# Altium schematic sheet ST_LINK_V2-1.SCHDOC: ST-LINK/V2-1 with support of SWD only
size A4; Date: 25-FEB-2015; Author: A.B; CompanyName: STMicroelectronics; Address1: 12, Rue Jules HOROWITZ; Address2: 38019 Grenoble; Address3: FRANCE; DocumentNumber: MB1191; Revision: B-02; SheetNumber: 2; SheetTotal: 13; Project: STM32F746G-DISCO
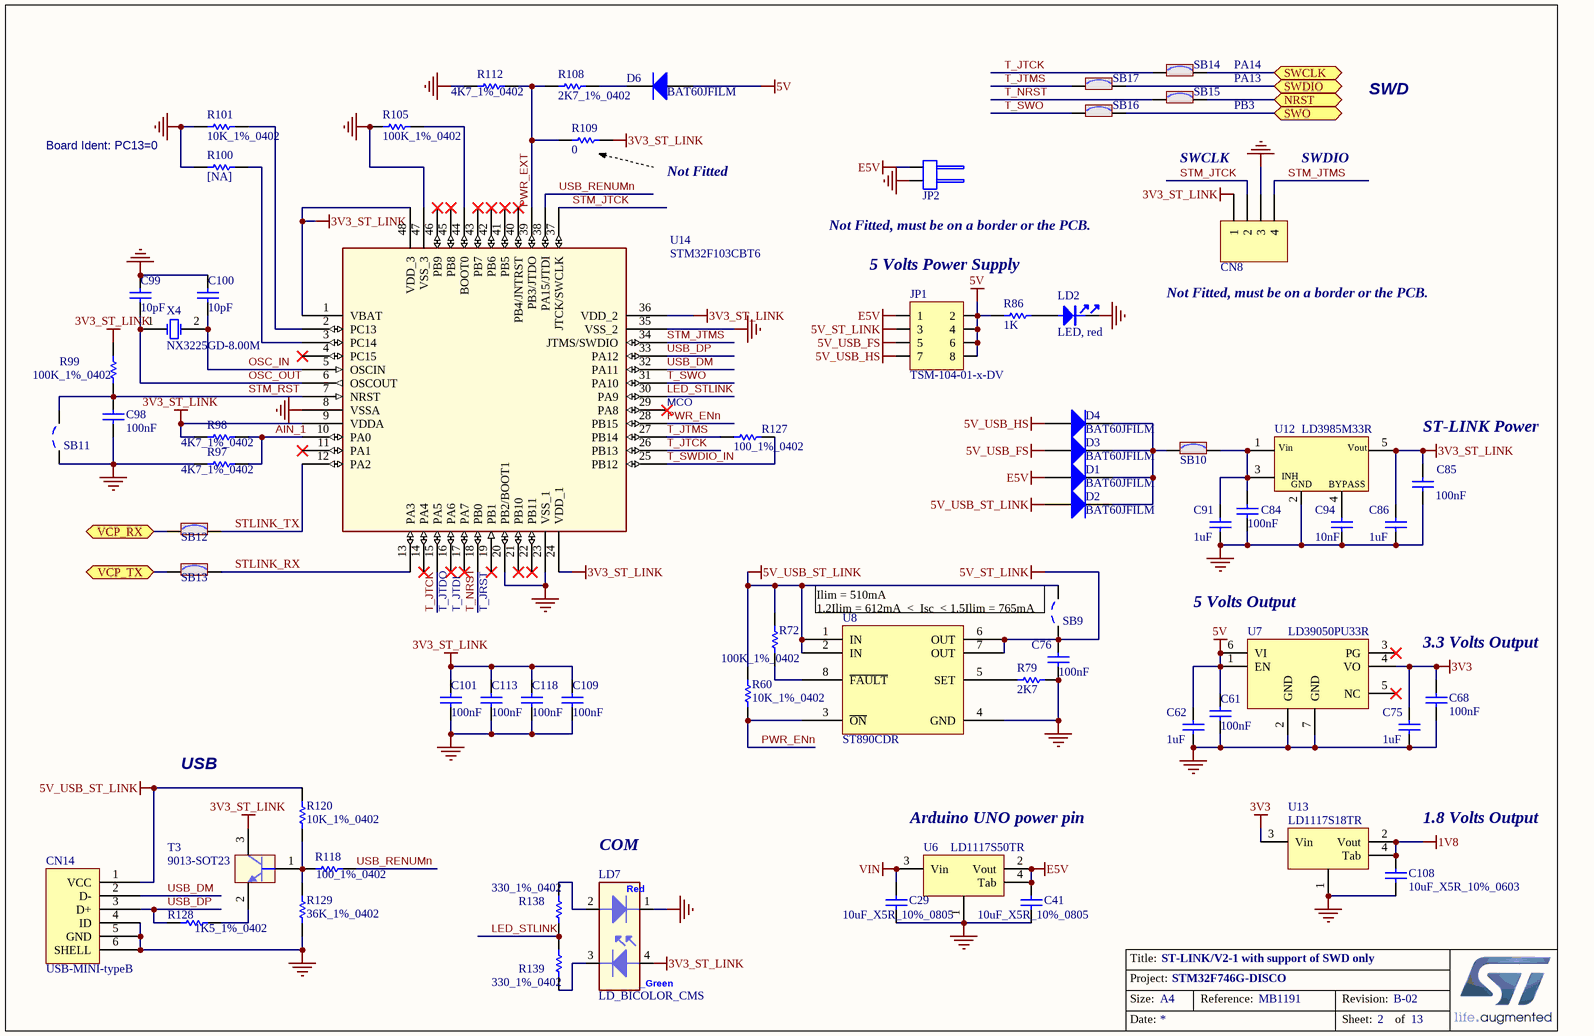
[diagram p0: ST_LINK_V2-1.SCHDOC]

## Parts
C29  10uF_X5R_10%_0805  [0805C]
C41  10uF_X5R_10%_0805  [0805C]
C61  100nF  [0402C]
C62  1uF  [0603C]
C68  100nF  [0402C]
C75  1uF  [0603C]
C76  100nF  [0402C]
C84  100nF  [0402C]
C85  100nF  [0402C]
C86  1uF  [0603C]
C91  1uF  [0603C]
C94  10nF  [0603C]
C98  100nF  [0402C]
C99  10pF  [0402C]
C100  10pF  [0402C]
C101  100nF  [0402C]
C108  10uF_X5R_10%_0603  [0603C]
C109  100nF  [0402C]
C113  100nF  [0402C]
C118  100nF  [0402C]
CN8  Header 4  [Header 4]  (value not drawn)
CN14  USB-MINI-typeB  [USB-MINI-B-SMD]
D1  BAT60JFILM  [SOD323/A]
D2  BAT60JFILM  [SOD323/A]
D3  BAT60JFILM  [SOD323/A]
D4  BAT60JFILM  [SOD323/A]
D6  BAT60JFILM  [SOD323/A]
JP1  TSM-104-01-x-DV  [TSM-104-01-x-DV]
JP2  TSM-102-01-x-SH  [SL_12_SMD_032_2]  (value not drawn)
LD2  LED, red  [0603D]
LD7  LD_BICOLOR_CMS  [HSMF-A201]
R60  10K_1%_0402  [0402R]
R72  100K_1%_0402  [0402R]
R79  2K7  [0402R]
R86  1K  [0402R]
R97  4K7_1%_0402  [0402R]
R98  4K7_1%_0402  [0402R]
R99  100K_1%_0402  [0402R]
R100  [NA]  [0402R]
R101  10K_1%_0402  [0402R]
R105  100K_1%_0402  [0402R]
R108  2K7_1%_0402  [0402R]
R109  0  [0402R]
R112  4K7_1%_0402  [0402R]
R118  100_1%_0402  [0402R]
R120  10K_1%_0402  [0402R]
R127  100_1%_0402  [0402R]
R128  1K5_1%_0402  [0402R]
R129  36K_1%_0402  [0402R]
R138  330_1%_0402  [0402R]
R139  330_1%_0402  [0402R]
SB9  Solder Bridge OFF  [JP2_SMD]  (value not drawn)
SB10  Solder Bridge ON  [JP2_SMD]  (value not drawn)
SB11  Solder Bridge OFF  [JP2_SMD]  (value not drawn)
SB12  Solder Bridge ON  [JP2_SMD]  (value not drawn)
SB13  Solder Bridge ON  [JP2_SMD]  (value not drawn)
SB14  Solder Bridge ON  [JP2_SMD]  (value not drawn)
SB15  Solder Bridge ON  [JP2_SMD]  (value not drawn)
SB16  Solder Bridge ON  [JP2_SMD]  (value not drawn)
SB17  Solder Bridge ON  [JP2_SMD]  (value not drawn)
T3  9013-SOT23  [SOT23]
U6  LD1117S50TR  [SOT-223]
U7  LD39050PU33R  [DFN6_3x3]
U8  ST890CDR  [SO-8]
U12  LD3985M33R  [SOT-23-5L]
U13  LD1117S18TR  [SOT-223]
U14  STM32F103CBT6  [QFP48 7x7]
X4  NX3225GD-8.00M  [XTAL_2SM_3R2X2R5]

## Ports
NRST, SWCLK, SWDIO, SWO, VCP_RX, VCP_TX

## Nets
1V8: C108.2 U13.2(Vout) U13.4(Tab)
3V3: C68.2 C75.2 U7.4(VO) U13.3(Vin)
3V3_ST_LINK: C85.2 C86.1 C101.2 C109.2 C113.2 C118.1 CN8.1 LD7.4 R98.1 R99.2 R109.2 T3.3(C) U12.5(Vout) U14.1(VBAT) U14.9(VDDA) U14.24(VDD_1) U14.36(VDD_2) U14.48(VDD_3)
5V: C61.2 C62.2 D6.1(A) JP1.2 JP1.4 JP1.6 JP1.8 R86.1 U7.1(EN) U7.6(VI)
5V_ST_LINK: C76.2 JP1.3 SB9.1 U8.6(OUT) U8.7(OUT)
5V_USB_FS: D3.1(A) JP1.5
5V_USB_HS: D4.1(A) JP1.7
5V_USB_ST_LINK: CN14.1(VCC) D2.1(A) R60.2 R72.2 R120.2 SB9.2 U8.1(IN) U8.2(IN)
E5V: C41.2 D1.1(A) JP1.1 JP2.1(COMMON) U6.2(Vout) U6.4(Tab)
GND: C29.1 C41.1 C61.1 C62.1 C68.1 C75.1 C76.1 C84.1 C85.1 C86.2 C91.1 C94.1 C98.1 C99.1 C100.1 C101.1 C108.1 C109.1 C113.1 C118.2 CN8.3 CN14.4(ID) CN14.5(GND) CN14.6(SHELL) JP2.2(NO) LD2.2 LD7.1 R79.2 R97.1 R100.1 R101.1 R105.1 R112.1 R129.1 SB11.1 U6.1 U7.2(GND) U7.7(GND) U8.4(GND) U12.2(GND) U13.1 U14.8(VSSA) U14.20(PB2/BOOT1) U14.23(VSS_1) U14.35(VSS_2) U14.47(VSS_3)
VIN: C29.2 U6.3(Vin)
AIN_1: R97.2 R98.2 U14.10(PA0)
LED_STLINK: R138.1 R139.2 U14.30(PA9)
NRST: SB15.2 ; port NRST
OSC_IN: C100.2 U14.5(OSCIN) X4.2(OSC2)
OSC_OUT: C99.2 U14.6(OSCOUT) X4.1(OSC1)
PWR_ENn: R60.1 U8.3(~{ON}) U14.28(PB15)
PWR_EXT: R108.1 R109.1 R112.2 U14.39(PB3/JTDO)
STLINK_RX: SB13.2 U14.13(PA3)
STLINK_TX: SB12.2 U14.12(PA2)
STM_JTCK: CN8.2 U14.37(JTCK/SWCLK)
STM_JTMS: CN8.4 U14.34(JTMS/SWDIO)
STM_RST: C98.2 R99.1 SB11.2 U14.7(NRST)
SWCLK: SB14.2 ; port SWCLK
SWDIO: SB17.2 ; port SWDIO
SWO: SB16.2 ; port SWO
T_JTCK: SB14.1 U14.15(PA5) U14.26(PB13)
T_JTMS: R127.1 SB17.1 U14.27(PB14)
T_NRST: SB15.1 U14.18(PB0)
T_SWDIO_IN: R127.2 U14.25(PB12)
T_SWO: SB16.1 U14.31(PA10)
USB_DM: CN14.2(D-) U14.32(PA11)
USB_DP: CN14.3(D+) R128.1 U14.33(PA12)
USB_RENUMn: R118.2 U14.38(PA15/JTDI)
VCP_RX: SB12.1 ; port VCP_RX
VCP_TX: SB13.1 ; port VCP_TX
NetC84_2: C84.2 C91.2 SB10.2 U12.1(Vin) U12.3(CE)
NetC94_2: C94.2 U12.4(BYPASS)
NetD1_2: D1.2(K) D2.2(K) D3.2(K) D4.2(K) SB10.1
NetD6_2: D6.2(K) R108.2
NetLD2_1: LD2.1 R86.2
NetLD7_2: LD7.2 R138.2
NetLD7_3: LD7.3 R139.1
NetR72_1: R72.1 U8.8(~{FAULT})
NetR79_1: R79.1 U8.5(SET)
NetR100_2: R100.2 U14.3(PC14)
NetR101_2: R101.2 U14.2(PC13)
NetR105_2: R105.2 U14.44(BOOT0)
NetR118_1: R118.1 R120.1 R129.2 T3.1(B)
NetR128_2: R128.2 T3.2(E)

Not connected (* = marked no-connect by the designer): U7 3(PG)* 5(NC)*; U14 4(PC15)* 11(PA1)* 14(PA4)* 16(PA6)* 17(PA7)* 19(PB1)* 21(PB10)* 22(PB11)* 29(PA8)* 40(PB4/JNTRST)* 41(PB5)* 42(PB6)* 43(PB7)* 45(PB8)* 46(PB9)*

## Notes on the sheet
- PA14
- PA13
- PB3
- SWD
- Board Ident: PC13=0
- Not Fitted
- SWCLK
- SWDIO
- (near JP2) Not Fitted, must be on a border or the PCB.
- 5 Volts Power Supply
- Not Fitted, must be on a border or the PCB.
- MCO
- ST-LINK Power
- (near U14) T_JTDO
- (near U14) T_JTDI
- (near U14) T_JRST
- (near SB9) Ilim = 510mA
  1.2Ilim = 612mA  <  Isc  < 1.5Ilim = 765mA
- 5 Volts Output
- 3.3 Volts Output
- USB
- COM
- (near U6) Arduino UNO power pin
- 1.8 Volts Output

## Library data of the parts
C29 C41 = Cap_10uF_X5R_10%_0805: Capacitor,10uF,25V,X5R,10%,0805,YAGEO; Manuf_Part_1: CC0805KRX5R8BB106
C61 C68 C76 C84 C85 C98 C101 C109 C113 C118 = Cap_100nF_X7R_10%_0402: Capacitor,100nF,16V,X7R,10%,0402,YAGEO; Manuf_Part_1: CC0402KRX7R7BB104
C62 C75 C86 C91 = Cap_1uF_X5R_10%_0603: Capacitor,1uF,16V,X5R,10%,0603,YAGEO; Manuf_Part_1: CC0603KRX5R7BB105
C94 = Cap_10nF_X7R_10%_0603: Capacitor,10nF,50V,X7R,10%,0603,YAGEO; Manuf_Part_1: CC0603KRX7R9BB103
C99 C100 = Cap_10pF_NPO_5%_0402: Capacitor,10pF,50V,NPO,5%,0402,YAGEO; Order: CC0402JRNPO9BN100
C108 = Cap_10uF_X5R_10%_0603: Capacitor,10uF,6.3V,X5R,10%,0603,YAGEO; Manuf_Part_1: CC0603KRX5R5BB106
CN8 = Header 4: Header, 4-Pin; Fitted: NO
CN14 = USB-MINI-typeB connector: Manuf_Part_1: 5075BMR-05-SM; Manuf_Part_2: 218205M1110T; Manuf_2: lyconn; Manuf_Part_3: MUSB5QS-BM1H6-NLB-E; Manuf_3: TOWNES; Description: USB,MINI-USB-5P/F, 5075BMR-05-M
D1-D4 D6 = BAT60JFILM: Manuf_1: STM; Provided: ST; ECCN_US/EU: EAR99/NEC; Ref St: 9151097
JP1 = Header_4X2_SMD: Header, 4-Pins, Double row Vertical, SMD, 2.54; Manuf_1: SAMTEC
JP2 = JP2_CMS: Header, 2-Pins, Single row Horizontal SMD, 2.54; Manuf_1: SAMTEC; Manuf_Part_2: SL 12 SMD 032 2 Z B TR; Manuf_2: Fisher Elektronik; Manuf_Part_3: P1014-1*02VGF-129-1A; Manuf_3: TOWNES
LD2 = LED_red: LED, red, 0603; Manuf_1: everlight; Manuf_Part_1: 19-213-R6C-AP1Q2B/3T; Description: LED,red,0603,19-213-R6C-AP1Q2B/3T,everlight; ECCN_US/EU: EAR99/NEC
LD7 = LD_BICOLOR_CMS: Bicolor Led; Manuf_Part_1: HSMF-A201-A00J1; Manuf_1: Avago Technologies; Manuf_2: everluck; Manuf_Part_2: LE-RGW35280; Ref St: xxxxxx; ECCN_US/EU: EAR99/NEC
R60 R101 R120 = Res_10K_1%_0402: Resistor,10K,0402,1%,YAGEO; Manuf_Part_1: RC0402FR-0710KL
R72 R99 R105 = Res_100K_1%_0402: Resistor,100K,0402,1%,YAGEO; Manuf_Part_1: RT0402FRE07100KL
R79 R108 = Res_2K7_1%_0402: Resistor,2K7,0402,1%,YAGEO; Manuf_Part_1: RC0402FR-072K7L
R86 = Res_1K_1%_0402: Resistor,1K,0402,1%,YAGEO; Manuf_Part_1: RC0402FR-071KL
R97 R98 R112 = Res_4K7_1%_0402: Resistor,4K7,0402,1%,YAGEO; Manuf_Part_1: RT0402FRE074K7L
R100 = Res_NA_0402: Resistor,[NA],0402; Fitted: NO
R109 = Res_0_5%_0402: Resistor,0,0402,5%,YAGEO; Manuf_Part_1: RC0402JR-070RL; Order: 2363467; Fitted: NO
R118 R127 = Res_100_1%_0402: Resistor,100,0402,1%,YAGEO; Manuf_Part_1: RC0402FR-07100RL; Value: 100; Order: 9239111
R128 = Res_1K5_1%_0402: Resistor,1K5,0402,1%,YAGEO; Manuf_Part_1: RC0402FR-071K5L
R129 = Res_36K_1%_0402: Resistor,36K,0402,1%,YAGEO; Manuf_Part_1: RC0402FR-0736KL
R138 R139 = Res_330_1%_0402: Resistor,330,0402,1%,YAGEO; Manuf_Part_1: RC0402FR-07330RL; Value: 330
SB9 SB11 = SB_OFF: Solder: NO
SB10 SB12-SB17 = SB_ON: Solder: YES
T3 = 9013-SOT23: NPN Bipolar Transistor; Manuf_1: NXP; Manuf_Part_1: BSR14; Description: NPN Bipolar Transistor, SOT-23 Footprint; Order: 1081310; ECCN_US/EU: EAR99/NEC
U6 = LD1117S50TR: IC REG LDO 5V 0.8A SOT223; Manuf_1: STM; Ordered by: ST; ECCN_US/EU: EAR99/NEC; Ref St: 9176133
U7 = LD39050P: Ultra low drop-low , 500 mA low quiescent current; Manuf_1: STM; Provided: ST; ECCN_US/EU: EAR99/NEC; Ref St: xxxxxxxx
U8 = ST890CDR: 1.2 A current limited high-side power switch with thermal shutdown; Manuf_1: STM; ECCN_US/EU: EAR99/NEC; Provided: ST
U12 = LD3985M33R: Ultra low drop-low noise BiCMOS voltage, regulators low ESR capacitors compatible; Manuf_1: STM; Provided: ST; Ref St: 9176161; ECCN_US/EU: EAR99/NEC
U13 = LD1117S18TR: LOW DROP FIXED AND ADJUSTABLE POSITIVE VOLTAGE REGULATORS (1.8 Volts); Manuf_1: STM; Ref St: 9176180; ECCN_US/EU: EAR99/NEC; Provided: ST
U14 = STM32F103CBT6: Medium-density performance line ARM-based 32-bit MCU with 128KB Flash; Manuf_1: STM; Ref St: xxxxxxxx; Provided: ST; ECCN_US/EU: 3A991A2/NEC
X4 = XTAL_8M_NX3225GD: Crystal 8Mhz, 8pF, -+50PPM, SMD; Manuf_1: NDK; Manuf_Part_1: NX3225GD 8MHz EXS00A-CG04874; Manuf_Part_2: NX3225GD-8.000M-STD-CRA-3; ECCN_US/EU: EAR99/NEC; NDK Ref: X3127326; Ref St: 9157029; Provided: ST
